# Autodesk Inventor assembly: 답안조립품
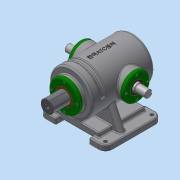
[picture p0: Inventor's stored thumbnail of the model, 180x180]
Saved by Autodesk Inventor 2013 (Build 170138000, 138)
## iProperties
Created: 2018-06
Part Number: 답안조립품
Document SubType Name: Assembly
Designer: Administrator
Mass: 8560.47 g
Surface Area: 4294.68 cm^2
Volume: 2307.06 cm^3
Density: 3.71055 g/cm^3
Author: Administrator
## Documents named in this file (13)
- C:\Users\Administrator\Desktop\380628V1009\답안조립품.iam
- C:\Users\Administrator\Desktop\380628V1009\본체.ipt
- C:\Users\Administrator\Desktop\380628V1009\가변스프링.ipt
- C:\Users\Administrator\Desktop\380628V1009\베어링 6205.ipt
- 베어링 6205.ipt
- C:\Users\Administrator\Desktop\380628V1009\볼트 M4.ipt
- C:\Users\Administrator\Desktop\380628V1009\부시.ipt
- C:\Users\Administrator\Desktop\380628V1009\슬라이드 커버.ipt
- C:\Users\Administrator\Desktop\380628V1009\슬라이드.ipt
- C:\Users\Administrator\Desktop\380628V1009\오일실.ipt
- 오일실.ipt
- C:\Users\Administrator\Desktop\380628V1009\축 커버.ipt
- C:\Users\Administrator\Desktop\380628V1009\편심축.ipt
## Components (1 placed, 1 different names)
1. 가변스프링:1
